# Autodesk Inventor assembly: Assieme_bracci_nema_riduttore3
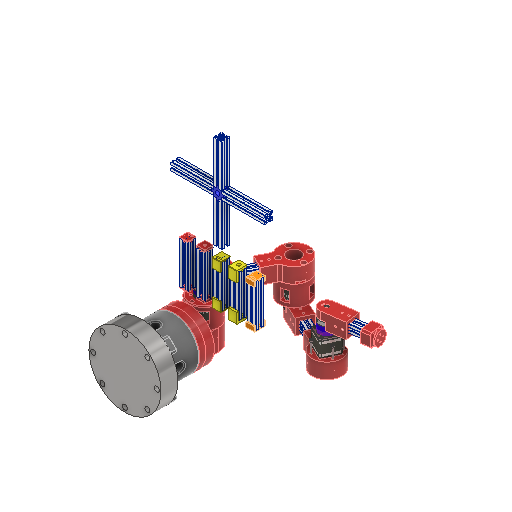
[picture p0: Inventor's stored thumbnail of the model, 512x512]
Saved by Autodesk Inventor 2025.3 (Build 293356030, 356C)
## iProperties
Created: 2026-01
Part Number: Assieme_bracci_nema_riduttore3
Document SubType Name: Assembly
Designer: Ryzen5700u
Author: Ryzen5700u
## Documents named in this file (18)
- C:\Users\R5800u\Desktop\3d\antropomorfo_nema4\Assieme_bracci_nema_riduttore4.iam
- C:\Users\R5800u\Desktop\3d\antropomorfo_nema4\blocco_nema_riduttore.iam
- C:\Users\R5800u\Desktop\3d\antropomorfo_nema4\tslot-20x20-3.ipt
- C:\Users\R5800u\Desktop\3d\antropomorfo_nema4\blocco_nema2.ipt
- C:\Users\R5800u\Desktop\3d\antropomorfo_nema4\blocco_nema_riduttore2.iam
- C:\Users\R5800u\Desktop\3d\antropomorfo_nema4\blocco_base.ipt
- C:\Users\R5800u\Desktop\3d\antropomorfo_nema4\tslot-20x20-4.ipt
- C:\Users\R5800u\Desktop\3d\antropomorfo_nema4\base_ferro.ipt
- C:\Users\R5800u\Desktop\3d\antropomorfo_nema4\tslot-20x20-5.ipt
- C:\Users\R5800u\Desktop\3d\antropomorfo_nema4\terminale.ipt
- C:\Users\R5800u\Desktop\3d\antropomorfo_nema4\NEMA 17HS4401S-PG518.ipt
- C:\Users\R5800u\Desktop\3d\antropomorfo_nema4\base_01.ipt
- C:\Users\R5800u\Desktop\3d\antropomorfo_nema4\maschera.ipt
- C:\Users\R5800u\Documents\Inventor\Content Center Files\R2025\it-IT\UNI ISO 104\ISO 104 - 1 11 50 x 70 x 14.ipt
- C:\Users\R5800u\Desktop\3d\antropomorfo_nema4\blocco_alto_base.ipt
- C:\Users\R5800u\Documents\Inventor\Content Center Files\R2025\it-IT\AS 1112 (2)\AS 1112 - M5  Tipo 5.ipt
- C:\Users\R5800u\Documents\Inventor\Content Center Files\R2025\it-IT\ANSI B18.3.1M(6)\ANSI B18.3.1M - M5x0,8 x 30(1).ipt
- C:\Users\R5800u\Desktop\3d\antropomorfo_nema4\Assieme_tappo_tslot.iam
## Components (29 placed, 17 different names)
1. tslot-20x20-3:1 — Coincidente:12, Coincidente:13, Coincidente:14, Coincidente:26, Coincidente:27, Coincidente:28
2. blocco_nema_riduttore2:3 [sub-assembly] — Coincidente:38, Coincidente:41, Coincidente:43, Coincidente:44, Coincidente:45, Coincidente:46
3. blocco_nema_riduttore:2 [sub-assembly] — Coincidente:12, Coincidente:13, Coincidente:14, Coincidente:24, Coincidente:25, Coincidente:42
4. blocco_base:1
5. tslot-20x20-5:1 — Coincidente:32, Coincidente:33, Coincidente:34, Coincidente:35, Coincidente:36, Coincidente:37
6. blocco_nema2:1 — Coincidente:26, Coincidente:27, Coincidente:28, Coincidente:29, Coincidente:30, Coincidente:31
7. blocco_nema_riduttore2:4 [sub-assembly] — Coincidente:29, Coincidente:30, Coincidente:31, Coincidente:32, Coincidente:33, Coincidente:34
8. blocco_nema2:2 — Coincidente:35, Coincidente:36, Coincidente:37, Coincidente:38, Coincidente:41, Coincidente:46
9. tslot-20x20-4:1 — Coincidente:43, Coincidente:44, Coincidente:45, Coincidente:47, Coincidente:48, Coincidente:49
10. terminale:1 — Coincidente:47, Coincidente:48, Coincidente:49
11. NEMA 17HS4401S-PG518:1 — Angolo:3, Coincidente:56, Coincidente:57
12. base_01:1
13. base_ferro:1 — Allineato:1, Allineato:2, Angolo:4, Coincidente:60, Coincidente:61
14. maschera:1 — Allineato:1, Allineato:2
15. UNI ISO 104 1 11 50 x 70 x 14:2 — Rotazionale:4, Coincidente:54
16. blocco_alto_base:2 — Coincidente:54, Coincidente:55, Angolo:5, Coincidente:59
17. Vite forgiata a testa incassata - Metrico M5x0,8 x 30:1
18. Vite forgiata a testa incassata - Metrico M5x0,8 x 30:2
19. Vite forgiata a testa incassata - Metrico M5x0,8 x 30:3
20. Vite forgiata a testa incassata - Metrico M5x0,8 x 30:4
21. Vite forgiata a testa incassata - Metrico M5x0,8 x 30:5
22. Vite forgiata a testa incassata - Metrico M5x0,8 x 30:6
23. Vite forgiata a testa incassata - Metrico M5x0,8 x 30:7
24. Vite forgiata a testa incassata - Metrico M5x0,8 x 30:8
25. Assieme_tappo_tslot:1 [sub-assembly]
26. AS 1112 (2) - Metrico M5  Tipo 5:1
27. AS 1112 (2) - Metrico M5  Tipo 5:2
28. AS 1112 (2) - Metrico M5  Tipo 5:3
29. AS 1112 (2) - Metrico M5  Tipo 5:4
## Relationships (40: Mate 34, Angle 3, Flush 2, RevoluteJoint 1)
- Coincidente:12 [Mate]: tslot-20x20-3:1 ↔ blocco_nema_riduttore:2
- Coincidente:13 [Mate]: tslot-20x20-3:1 ↔ blocco_nema_riduttore:2
- Coincidente:14 [Mate]: tslot-20x20-3:1 ↔ blocco_nema_riduttore:2
- Coincidente:24 [Mate]: blocco_nema_riduttore:2
- Coincidente:25 [Mate]: blocco_nema_riduttore:2
- Coincidente:26 [Mate]: tslot-20x20-3:1 ↔ blocco_nema2:1
- Coincidente:27 [Mate]: tslot-20x20-3:1 ↔ blocco_nema2:1
- Coincidente:28 [Mate]: tslot-20x20-3:1 ↔ blocco_nema2:1
- Coincidente:29 [Mate]: blocco_nema2:1 ↔ blocco_nema_riduttore2:4
- Coincidente:30 [Mate]: blocco_nema2:1 ↔ blocco_nema_riduttore2:4
- Coincidente:31 [Mate]: blocco_nema2:1 ↔ blocco_nema_riduttore2:4
- Coincidente:32 [Mate]: tslot-20x20-5:1 ↔ blocco_nema_riduttore2:4
- Coincidente:33 [Mate]: tslot-20x20-5:1 ↔ blocco_nema_riduttore2:4
- Coincidente:34 [Mate]: tslot-20x20-5:1 ↔ blocco_nema_riduttore2:4
- Coincidente:35 [Mate]: tslot-20x20-5:1 ↔ blocco_nema2:2
- Coincidente:36 [Mate]: tslot-20x20-5:1 ↔ blocco_nema2:2
- Coincidente:37 [Mate]: tslot-20x20-5:1 ↔ blocco_nema2:2
- Coincidente:38 [Mate]: blocco_nema_riduttore2:3 ↔ blocco_nema2:2
- Coincidente:41 [Mate]: blocco_nema_riduttore2:3 ↔ blocco_nema2:2
- Coincidente:42 [Mate]: blocco_nema_riduttore:2
- Coincidente:43 [Mate]: blocco_nema_riduttore2:3 ↔ tslot-20x20-4:1
- Coincidente:44 [Mate]: blocco_nema_riduttore2:3 ↔ tslot-20x20-4:1
- Coincidente:45 [Mate]: blocco_nema_riduttore2:3 ↔ tslot-20x20-4:1
- Coincidente:46 [Mate]: blocco_nema_riduttore2:3 ↔ blocco_nema2:2
- Coincidente:47 [Mate]: tslot-20x20-4:1 ↔ terminale:1
- Coincidente:48 [Mate]: tslot-20x20-4:1 ↔ terminale:1
- Coincidente:49 [Mate]: tslot-20x20-4:1 ↔ terminale:1
- Allineato:1 [Flush]: base_ferro:1 ↔ maschera:1
- Allineato:2 [Flush]: base_ferro:1 ↔ maschera:1
- Rotazionale:4 [RevoluteJoint]: UNI ISO 104 1 11 50 x 70 x 14:2
- Angolo:3 [Angle]: NEMA 17HS4401S-PG518:1
- Angolo:4 [Angle]: base_ferro:1
- Coincidente:54 [Mate]: UNI ISO 104 1 11 50 x 70 x 14:2 ↔ blocco_alto_base:2
- Coincidente:55 [Mate]: blocco_alto_base:2
- Angolo:5 [Angle]: blocco_alto_base:2
- Coincidente:56 [Mate]: NEMA 17HS4401S-PG518:1
- Coincidente:57 [Mate]: NEMA 17HS4401S-PG518:1
- Coincidente:59 [Mate]: blocco_alto_base:2
- Coincidente:60 [Mate]: base_ferro:1
- Coincidente:61 [Mate]: base_ferro:1
